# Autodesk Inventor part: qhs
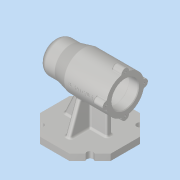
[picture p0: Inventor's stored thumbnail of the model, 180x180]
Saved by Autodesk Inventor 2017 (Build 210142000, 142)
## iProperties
Created: 2019-12
Part Number: qhs
Material: 알루미늄 6061
Document SubType Name: Modeling
Designer: 5-15-le-1
Density: 2.7 g/cm^3
Appearance: 알루미늄 - 평지
Mass: 725.664 g
Surface Area: 714.987 cm^2
Volume: 268.764 cm^3
Author: 5-15-le-1
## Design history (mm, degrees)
sketch "스케치3" dims "d0" = 112
  geometry: L1 (-56, -23.196)-(-56, 23.196); L2 (-56, 23.196)-(-23.196, 56); L3 (-23.196, 56)-(23.196, 56); L4 (23.196, 56)-(56, 23.196); L5 (56, 23.196)-(56, -23.196); L6 (56, -23.196)-(23.196, -56); L7 (23.196, -56)-(-23.196, -56); L8 (-23.196, -56)-(-56, -23.196); 4 further points
  constraints: 16 end point, 2 coincident, 1 horizontal, 1 midpoint, 20 other
extrude "돌출1" new body sketch "스케치3" distance "d1" = 10; taper "d2" = 0 deg
sketch "스케치4"
  geometry: L1 (56, 23.196)-(23.196, 56) reference; L2 (-23.196, 56)-(-56, 23.196) reference; L3 (23.196, -56)-(56, -23.196) reference; L4 (-23.196, -56)-(-56, -23.196) reference; C1 r 5 at (-39.598, -39.598); C2 r 5 at (-39.598, 39.598); C3 r 5 at (39.598, 39.598); C4 r 5 at (39.598, -39.598); 1 further point
  constraints: 4 centre point, 4 midpoint, 3 equal radius
  dimensions: "d3" = 10 diameter of C1
extrude "돌출2" cut sketch "스케치4" stored distance "d4" = 10; taper "d5" = 0 deg
sketch "스케치5"
  geometry: L1 (56, 110)-(-11, 110); L2 (-11, 110)-(-31, 105); L3 (-31, 105)-(-56, 105); L4 (-56, 80)-(56, 80); L5 (56, 80)-(56, 110); L6 (-56, 105)-(-56, 80); L7 (56, 0)-(43.134, 0) reference; 2 further points
  constraints: 12 end point, 2 horizontal, 1 parallel, 1 perpendicular, 1 vertical, 1 vertical alignment
  dimensions: "d6" = 112 distance between parallel lines of L5 L6; "d7" = 25 distance of L2.end L3.end; "d8" = 45 distance from line of L6 L1.end; "d9" = 50 diameter of L3 L4; "d10" = 60 diameter of L1 L4; "d11" = 80 distance between parallel lines of L7 L4
revolve "회전1" sketch "스케치5" stored, may be unused: angle "d12" = 90 deg
sketch "스케치6"
  geometry: L1 (-14.685, 60)-(-38, 10); L2 (-56, 10)-(-43.134, 10) reference; L3 (-38, 10)-(31, 10); L4 (23.196, 10)-(36.062, 10) reference; L5 (31, 10)-(31, 60); L6 (31, 60)-(-14.685, 60); L7 (-56, 0)-(-56, 10) reference; L8 (56, 0)-(56, 10) reference; L9 (-11, 50)-(-11, 110) reference; L10 (56, 50)-(56, 110) reference; 1 further point
  constraints: 8 end point, 2 point on line, 1 perpendicular, 1 vertical
  dimensions: "d13" = 115 deg angle of L2 L1; "d14" = 18 distance from line of L7 L1.end; "d15" = 25 distance between parallel lines of L8 L5; "d16" = 10 distance from line of L9.start L6
extrude "돌출3" join sketch "스케치6" stored distance "d17" = 8; taper "d18" = 0 deg
sketch "스케치7"
  geometry: L1 (56.766, 18.979)-(10, 36); L2 (10, 36)-(10, -36); L3 (10, -36)-(56.766, -18.979); L4 (10, -36.062)-(10, -23.196) reference; L5 (52.125, 4)-(50.268, 4) reference; L6 (50.268, -4)-(52.125, -4) reference; L7 (0, 56)-(10, 56) reference; L8 (0, -56)-(10, -56) reference; L9 (10, -56)-(10, -43.134) reference; L10 (10, 43.134)-(10, 56) reference; C1 r 25 at (80, 0) reference; A1 r 30 centre (80, 0) between (50.268, -4) and (50.268, 4) reference; 2 further points; 1 other entity
  constraints: 6 end point, 2 point on circle, 1 collinear, 1 other
  dimensions: "d19" = 20 distance from line of L7 L1.end; "d20" = 20 distance from line of L8 L2.end; "d21" = 110 deg angle of L9 L3; "d22" = 110 deg angle of L10 L1
extrude "돌출4" join sketch "스케치7" stored distance "d23" = 8; taper "d24" = 0 deg
sketch "스케치8"
  geometry: L1 (56, 50)-(56, 110) reference; L2 (56, 80)-(-56, 80); L3 (-56, 55)-(-56, 105) reference; L4 (-50, 80)-(-50, 90.5); L5 (-50, 90.5)-(-47, 90.5); L6 (-47, 90.5)-(-47, 96); L7 (-47, 96)-(-43, 96); L8 (-43, 96)-(-43, 97.5); L9 (-25, 97.5)-(-25, 101); L10 (-25, 101)-(-13, 101); L11 (-13, 101)-(-13, 104); L12 (-13, 104)-(41, 104); L13 (41, 104)-(41, 101); L14 (41, 101)-(56, 101); L15 (-43, 97.5)-(-25, 97.5); 1 further point
  constraints: 26 end point, 7 perpendicular, 2 midpoint, 2 point on line, 2 vertical, 1 horizontal, 1 parallel
  dimensions: "d25" = 42 diameter of L14 L2; "d26" = 15 distance of L13.end L14.end; "d27" = 48 diameter of L12 L2; "d28" = 54 distance of L11.end L12.end; "d29" = 12 distance of L9.end L10.end; "d30" = 42 diameter of L10 L2; "d31" = 18 distance of L8.end L9.start; "d32" = 35 diameter of L15 L2; "d33" = 4 distance of L6.end L7.end; "d34" = 3 distance of L4.end L5.end; "d35" = 32 diameter of L7 L2; "d36" = 21 diameter of L5 L2
revolve "회전2" sketch "스케치8" stored, may be unused: angle "d37" = 90 deg
sketch "스케치9"
  geometry: C1 r 6 at (0, 30); 2 further points
  constraints: 1 centre point, 1 vertical alignment, 1 other
  dimensions: "d38" = 12 diameter of C1
extrude "돌출5" join sketch "스케치9" distance "d39" = 16; taper "d40" = 0 deg
hole "구멍1" diameter "d43" = 3.459; stored, may be unused: countersink angle "d47" = 90 deg, drill point angle "d49" = 118 deg; dims "d41" = 10, "d42" = 10, "d44" = 8, "d45" = 4, "d46" = 2, "d48" = 11
fillet "모깎기1" dims "d50" = 3
fillet "모깎기2" dims "d52" = 1
fillet "모깎기3" dims "d56" = 0.3
fillet "모깎기4" dims "d57" = 3
chamfer "모따기1" distance "d58" = 1; stored, may be unused: second distance "d59" = 2, angle "d60" = 45 deg
fillet "모깎기5" dims "d61" = 10
fillet "모깎기6" dims "d62" = 3
fillet "모깎기7" dims "d63" = 3
fillet "모깎기8" dims "d64" = 3
node "작업 평면1"
sketch "스케치10"
  geometry: L1 (-28.5, 3.5)-(13.5, 3.5); L2 (13.5, 3.5)-(13.5, -3.5); L3 (13.5, -3.5)-(-28.5, -3.5); L4 (-28.5, -3.5)-(-28.5, 3.5); L5 (-28.5, 0)-(13.5, 0); L6 (-7.5, 3.5)-(-7.5, -3.5); L7 (33.5, -22)-(33.5, 22) reference; L8 (33.5, 0)-(-78.5, 0); L9 (-78.5, -15)-(-78.5, 15) reference; 1 further point
  constraints: 6 end point, 6 midpoint, 1 collinear, 2 other
  dimensions: "d65" = 42 distance of L1.start L1.end; "d66" = 7 distance of L1.end L2.end; "d67" = 41 distance between parallel lines of L7 L6
feature "엠보싱1" sketch "스케치10" dims "d3" = 10, "d68" = 0.5, "d69" = 0
node "솔리드1"
pattern_circular "원형 패턴1" dims "d54" = 360 deg
node "투영된 루프1"
node "투영된 루프2"
